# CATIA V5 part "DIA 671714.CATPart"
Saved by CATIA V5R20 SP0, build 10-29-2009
Part number: DIA 671714
Revision: ANY
Definition: UNKNOWN
Nomenclature: DIA 671714
Source: Unknown
Bounding box of the stored display mesh (mm): x -3.35 to 3.35, y -7.95 to 9.02, z -3.186 to 3.186
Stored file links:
  C:\Users\Utente\Desktop\IO LAVORO\3D X SITO CF\CUMSA\3D files FA\FA 126712-21\DIA 671714.CATPart
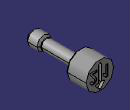
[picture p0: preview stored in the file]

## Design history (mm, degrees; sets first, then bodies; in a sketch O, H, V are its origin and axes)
Body1 "Cortar-Extruir4" (main body)
  Solid1: solid without history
